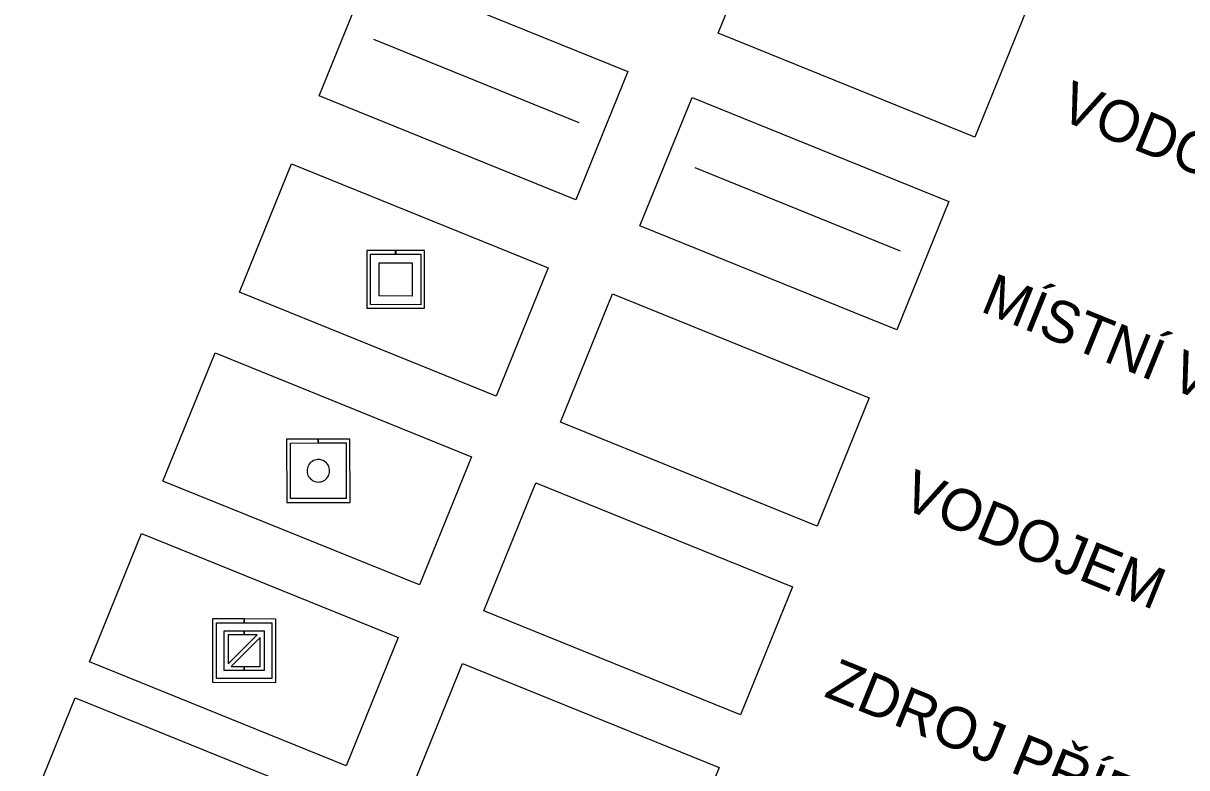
# Model space of a CAD drawing. Extents: x -522754 to -518969, y -1191121 to -1188171.
# Drawn here: x -520718.4 to -520298.2, y -1189892.9 to -1189624 of the extents above; entities that cross this region are included whole.
import ezdxf

# ---------------------------------------------------------------- set-up
doc = ezdxf.new("R2010")
doc.units = 0
for name, color, linetype in [('Implicitní', 7, 'Continuous'), ('ložisk_nerost', 7, 'Continuous'), ('zast_HD_s', 7, 'Continuous')]:
    doc.layers.add(name, color=color, linetype=linetype)

msp = doc.modelspace()

# ---------------------------------------------------------------- linework, layer by layer
at = {"layer": 'Implicitní'}
for p, q in [((-520591.9, -1189629.73), (-520517.76, -1189659.78)), ((-520475.87, -1189676.13), (-520401.72, -1189706.17))]:
    msp.add_line(p, q, dxfattribs=at)
for points in [[(-520448.71, -1189581.27), (-520356.03, -1189618.83), (-520374.81, -1189665.17), (-520467.49, -1189627.61)], [(-520592.72, -1189603.83), (-520500.05, -1189641.39), (-520518.83, -1189687.73), (-520611.5, -1189650.17)], [(-520476.88, -1189650.78), (-520384.2, -1189688.34), (-520402.98, -1189734.68), (-520495.66, -1189697.12)], [(-520621.46, -1189674.74), (-520528.79, -1189712.3), (-520547.57, -1189758.64), (-520640.24, -1189721.08)], [(-520505.62, -1189721.69), (-520412.94, -1189759.25), (-520431.72, -1189805.59), (-520524.4, -1189768.03)], [(-520649.12, -1189742.99), (-520556.45, -1189780.55), (-520575.23, -1189826.89), (-520667.91, -1189789.33)], [(-520533.28, -1189789.94), (-520440.6, -1189827.5), (-520459.38, -1189873.84), (-520552.06, -1189836.28)], [(-520675.61, -1189808.35), (-520582.94, -1189845.91), (-520601.72, -1189892.25), (-520694.39, -1189854.69)], [(-520559.77, -1189855.3), (-520467.09, -1189892.86), (-520485.87, -1189939.2), (-520578.55, -1189901.64)], [(-520699.57, -1189867.66), (-520606.89, -1189905.22), (-520625.67, -1189951.56), (-520718.35, -1189914)]]:
    msp.add_lwpolyline(points, close=True, dxfattribs=at)
at = {"layer": 'ložisk_nerost'}
for p, q in [((-520645.77, -1189857.8), (-520645.76, -1189843.42)), ((-520645.76, -1189843.42), (-520638.57, -1189843.43)), ((-520644.32, -1189844.86), (-520644.33, -1189855.35)), ((-520644.33, -1189855.35), (-520633.84, -1189844.87)), ((-520638.57, -1189844.87), (-520644.32, -1189844.86)), ((-520632.82, -1189845.88), (-520643.32, -1189856.36)), ((-520638.57, -1189843.43), (-520638.57, -1189844.87)), ((-520638.53, -1189844.87), (-520638.53, -1189843.43)), ((-520638.53, -1189843.43), (-520631.39, -1189843.43)), ((-520633.84, -1189844.87), (-520638.53, -1189844.87)), ((-520632.83, -1189856.37), (-520632.82, -1189845.88)), ((-520631.39, -1189843.43), (-520631.39, -1189857.81)), ((-520638.58, -1189857.8), (-520645.77, -1189857.8)), ((-520643.32, -1189856.36), (-520638.58, -1189856.37)), ((-520638.58, -1189856.37), (-520638.58, -1189857.8)), ((-520638.53, -1189857.8), (-520638.53, -1189856.37)), ((-520638.53, -1189856.37), (-520632.83, -1189856.37)), ((-520631.39, -1189857.81), (-520638.53, -1189857.8))]:
    msp.add_line(p, q, dxfattribs=at)
for points in [[(-520611.86, -1189774.18), (-520623.27, -1189774.21), (-520623.22, -1189797.09), (-520600.34, -1189797.04), (-520600.39, -1189774.16), (-520611.83, -1189774.18)], [(-520621.86, -1189775.62), (-520601.8, -1189775.57), (-520601.75, -1189795.64), (-520621.82, -1189795.68), (-520621.86, -1189775.62)], [(-520611.83, -1189775.59), (-520601.8, -1189775.57), (-520601.75, -1189795.63), (-520621.82, -1189795.68), (-520621.86, -1189775.61), (-520611.86, -1189775.59)], [(-520611.86, -1189775.59), (-520611.86, -1189774.18)], [(-520611.83, -1189774.18), (-520611.83, -1189775.59)], [(-520607.74, -1189785.62), (-520607.78, -1189785.11), (-520607.87, -1189784.6), (-520608.03, -1189784.11), (-520608.26, -1189783.65), (-520608.53, -1189783.22), (-520608.86, -1189782.82), (-520609.24, -1189782.47), (-520609.66, -1189782.17), (-520610.11, -1189781.93), (-520610.59, -1189781.75), (-520611.09, -1189781.62), (-520611.6, -1189781.57), (-520612.12, -1189781.57), (-520612.63, -1189781.64), (-520613.12, -1189781.78), (-520613.6, -1189781.98), (-520614.05, -1189782.23), (-520614.46, -1189782.54), (-520614.82, -1189782.9), (-520615.14, -1189783.3), (-520615.41, -1189783.74), (-520615.62, -1189784.21), (-520615.77, -1189784.7), (-520615.85, -1189785.21), (-520615.87, -1189785.72), (-520615.83, -1189786.24), (-520615.72, -1189786.74), (-520615.55, -1189787.22), (-520615.32, -1189787.68), (-520615.03, -1189788.11), (-520614.69, -1189788.5), (-520614.31, -1189788.84), (-520613.88, -1189789.13), (-520613.43, -1189789.36), (-520612.94, -1189789.53), (-520612.44, -1189789.65), (-520611.93, -1189789.69), (-520611.41, -1189789.67), (-520610.91, -1189789.59), (-520610.41, -1189789.45), (-520609.94, -1189789.24), (-520609.5, -1189788.98), (-520609.1, -1189788.66), (-520608.74, -1189788.29), (-520608.42, -1189787.88), (-520608.17, -1189787.44), (-520607.97, -1189786.96), (-520607.83, -1189786.47), (-520607.76, -1189785.96), (-520607.74, -1189785.62)], [(-520638.6, -1189839.17), (-520650.01, -1189839.17), (-520650.02, -1189862.05), (-520627.14, -1189862.06), (-520627.13, -1189839.18), (-520638.57, -1189839.17)], [(-520638.57, -1189840.58), (-520628.54, -1189840.59), (-520628.55, -1189860.65), (-520648.62, -1189860.64), (-520648.6, -1189840.57), (-520638.6, -1189840.58)], [(-520648.6, -1189840.58), (-520628.54, -1189840.59), (-520628.55, -1189860.65), (-520648.62, -1189860.64), (-520648.6, -1189840.58)], [(-520638.6, -1189840.58), (-520638.6, -1189839.17)], [(-520638.57, -1189839.17), (-520638.57, -1189840.58)]]:
    msp.add_lwpolyline(points, dxfattribs=at)
at = {"layer": 'zast_HD_s'}
for points in [[(-520583.89, -1189706.1), (-520594.26, -1189706.09), (-520594.29, -1189726.89), (-520573.49, -1189726.92), (-520573.46, -1189706.12), (-520583.86, -1189706.1)], [(-520583.87, -1189707.38), (-520574.75, -1189707.4), (-520574.77, -1189725.64), (-520593.01, -1189725.61), (-520592.99, -1189707.37), (-520583.89, -1189707.38)], [(-520592.99, -1189707.38), (-520574.75, -1189707.4), (-520574.77, -1189725.64), (-520593.01, -1189725.62), (-520592.99, -1189707.38)], [(-520583.89, -1189707.38), (-520583.89, -1189706.1)], [(-520583.86, -1189706.1), (-520583.87, -1189707.38)], [(-520589.85, -1189710.52), (-520577.88, -1189710.53), (-520577.9, -1189722.5), (-520589.87, -1189722.48), (-520589.85, -1189710.52)]]:
    msp.add_lwpolyline(points, dxfattribs=at)

# ---------------------------------------------------------------- texts
at = {"layer": 'Implicitní'}
for s, p in [('VODOVODNÍ ŘAD SKUPIN.VODOVODU', (-520345.07, -1189658.34)), ('MÍSTNÍ VODOVOD', (-520373.24, -1189727.85)), ('VODOJEM', (-520401.98, -1189798.76)), ('ZDROJ PŘÍRODNÍ PITNÉ VODY', (-520429.64, -1189867.01))]:
    msp.add_text(s, height=15, rotation=337.9379, dxfattribs=at).set_placement(p)

doc.saveas('drawing.dxf')
